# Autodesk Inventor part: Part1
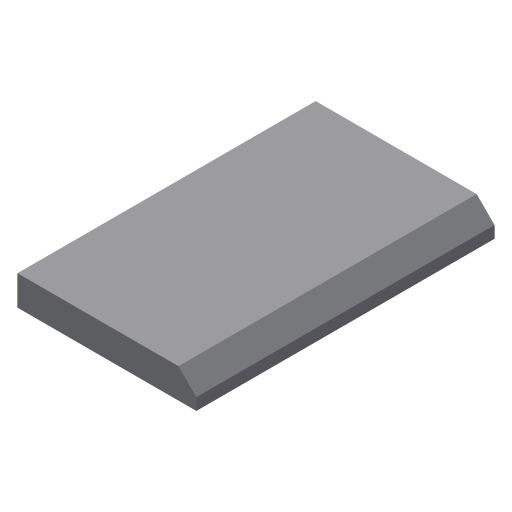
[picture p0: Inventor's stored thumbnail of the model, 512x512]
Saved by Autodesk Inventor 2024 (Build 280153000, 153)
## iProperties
Shininess: 64.0
Length Units: 11269
Angle Units: 11279
Time Units: 11290
Mass Units: 11283
Length Display Precision: 3
Angle Display Precision: 2
Compacted: True
Part Number: Part1
Document SubType Name: Modeling
Created: 2003-01
Designer: Owner
Density: 1 g/cm^3
Material: Generic
Appearance: Default
Density: 0.0
Volumn: 0.0
Area: 0.0
PropertySet Name: Model Information
Control State: 0
Master: False
Checked Out: False
Author: Owner
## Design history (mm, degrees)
sketch "Sketch1"
  geometry: L1 (-18.987, 24.241)-(11.013, 24.241); L2 (11.013, 24.241)-(11.013, -25.759); L3 (11.013, -25.759)-(-18.987, -25.759); L4 (-18.987, -25.759)-(-18.987, 24.241)
  constraints: 8 end point, 2 parallel, 1 horizontal, 1 perpendicular
  dimensions: "d0" = 30 distance of L1.start L1.end; "d1" = 50 distance of L3.end L1.start
extrude "Extrusion1" new body sketch "Sketch1" distance "d2" = 5; taper "d3" = 0 deg
chamfer "Chamfer1" distance "d4" = 3; stored, may be unused: second distance "d5" = 2, angle "d6" = 45 deg
body "Solid1"
